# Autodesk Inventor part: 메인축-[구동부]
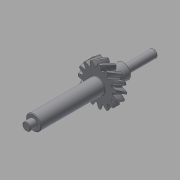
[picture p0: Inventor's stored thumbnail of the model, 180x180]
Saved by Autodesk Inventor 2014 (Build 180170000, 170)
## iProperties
Created: 2016-12
Part Number: 메인축-[구동부]
Material: 강철, 탄소
Document SubType Name: Modeling
Designer: mduedu
Categories: <?xml version="1.0" encoding="UTF-16"?> <MemberInstance><Categories><FamilyTemplate><FamilyTemplateParameter ValueType="xs:double" Id="1" ObjectReferenceKey="da
Density: 7.87 g/cm^3
Appearance: Default
Mass: 199.398 g
Surface Area: 86.9137 cm^2
Volume: 25.3365 cm^3
CustomPartVersion: 1
Author: mduedu
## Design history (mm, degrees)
sketch "Sketch1"
  geometry: C1 r 19.321 at (0, 0)
  constraints: 1 centre point
  dimensions: "d0" = 38.64102 diameter of C1 (= da_da)
extrude "Extrusion1" new body sketch "Sketch1" distance "d1" = 10 (= da_b); taper "d2" = 0 deg
workplane "Work Plane2"
sketch "Sketch2"
  geometry: C1 r 19.321 at (0, 0) reference; C2 r 17.321 at (0, 0)
  constraints: 1 centre point, 1 coincident
  dimensions: "d3" = 34.64102 diameter of C2 (= da_dw)
feature "피치 지름" sketch "Sketch2" dims "d4" = 10, "d5" = 0
workplane "Work Plane8"
workplane "Work Plane9"
feature "스퍼 기어" dims "da_b" = 10, "da_d" = 34.64102, "da_aw" = 43.87862, "da_da" = 38.64102, "da_df" = 29.64102, "da_dw" = 34.64102, angle "da_beta" = 30 deg, "da_lefttooth" = 0, "da_righttooth" = 10
sketch "스케치3"
  geometry: C1 r 7.5 at (0, 0); 1 further point
  constraints: 1 centre point, 1 coincident
  dimensions: "d49" = 15 diameter of C1
extrude "돌출2" join sketch "스케치3" distance "d50" = 64; taper "d51" = 0 deg
sketch "스케치4"
  geometry: C1 r 4 at (0, 0); 1 further point
  constraints: 1 centre point, 1 coincident
  dimensions: "d52" = 8 diameter of C1
extrude "돌출3" join sketch "스케치4" distance "d53" = 7; taper "d54" = 0 deg
sketch "스케치5"
  geometry: C1 r 7.5 at (0, 0) reference; 1 further point
extrude "돌출4" join sketch "스케치5" distance "d55" = 16; taper "d56" = 0 deg
sketch "스케치6"
  geometry: C1 r 4 at (0, 0); 1 further point
  constraints: 1 centre point, 1 coincident
  dimensions: "d57" = 8 diameter of C1
extrude "돌출5" join sketch "스케치6" distance "d58" = 30; taper "d59" = 0 deg
chamfer "모따기1" distance "d60" = 0.5; stored, may be unused: second distance "d61" = 2, angle "d62" = 45 deg
fillet "모깎기1" dims "d63" = 0.5
body "Solid1"
body "Srf1"
other parameters: "d16" = 43.87862 (= da_aw), "d17" = 0, "d34" = 12 deg (computed from da_z), "d39" = 0, "d41" = 0, "d43" = 43.87862 (= da_aw), "d46" = 43.87862 (= da_aw), "d47" = 0, "d48" = 0
